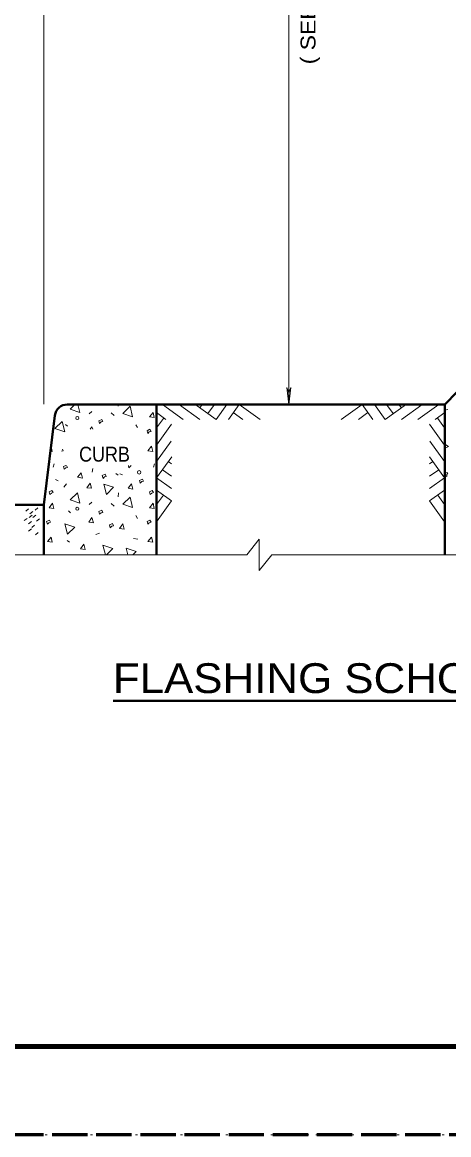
# Model space of a CAD drawing. Extents: x 312583 to 312854, y 144419 to 144597.
# Drawn here: x 312744.9 to 312766.7, y 144418.6 to 144475.3 of the extents above; entities that cross this region are included whole.
import ezdxf
from ezdxf.enums import TextEntityAlignment as Align

# ---------------------------------------------------------------- set-up
doc = ezdxf.new("R2010")
doc.units = 0
doc.header["$LTSCALE"] = 0.3
doc.linetypes.add('DOTTED', pattern=[1.5, 0.3, -1.2])
doc.linetypes.add('LONG_DASHED', pattern=[7.5, 6, -1.5])
for name, color, linetype, lineweight in [('1', 7, 'Continuous', 40), ('2', 7, 'Continuous', 13), ('62', 7, 'DOTTED', 13), ('63', 7, 'LONG_DASHED', 60)]:
    doc.layers.add(name, color=color, linetype=linetype, lineweight=lineweight)

msp = doc.modelspace()

# ---------------------------------------------------------------- linework, layer by layer
at = {"layer": '1'}
for p, q in [((312767.102, 144456.4563), (312766.4656, 144455.8123)), ((312766.4656, 144455.8123), (312747.2223, 144455.8123)), ((312751.7686, 144448.1456), (312751.7686, 144455.8123)), ((312766.4656, 144448.1456), (312766.4656, 144455.8123)), ((312746.586, 144455.2526), (312746.0186, 144450.7063)), ((312737.3329, 144450.7063), (312745.9655, 144450.7063)), ((312746.0186, 144448.1456), (312746.0186, 144450.7063))]:
    msp.add_line(p, q, dxfattribs=at)
at = {"layer": '1', "lineweight": 158}
msp.add_line((312616.5, 144423.0846), (312849, 144423.0846), dxfattribs=at)
at = {"layer": '1'}
msp.add_arc((312747.2222, 144455.1753), 0.6389, 90, 172.87498, dxfattribs=at)
at = {"layer": '2'}
for p, q in [((312746.0186, 144502.3183), (312746.0186, 144455.8276)), ((312758.5153, 144495.9933), (312758.5153, 144455.8123)), ((312758.408, 144456.6786), (312758.5153, 144456.4026)), ((312758.5153, 144455.8123), (312758.408, 144456.6786)), ((312758.408, 144456.6786), (312758.5153, 144456.4026)), ((312758.5153, 144455.8123), (312758.408, 144456.6786)), ((312758.6226, 144456.6786), (312758.5153, 144456.4026)), ((312758.5153, 144455.8123), (312758.6226, 144456.6786)), ((312758.6226, 144456.6786), (312758.5153, 144456.4026)), ((312758.5153, 144455.8123), (312758.6226, 144456.6786)), ((312748.334, 144455.3369), (312748.4796, 144455.4596)), ((312749.8213, 144455.8123), (312749.8136, 144455.7356)), ((312753.1333, 144455.0533), (312752.0676, 144455.8123)), ((312753.9766, 144455.0533), (312752.934, 144455.7969)), ((312754.8123, 144455.0533), (312753.7236, 144455.8276)), ((312754.0993, 144455.8123), (312753.9766, 144455.6436)), ((312754.728, 144455.8123), (312754.3906, 144455.3523)), ((312755.349, 144455.8123), (312754.8123, 144455.0533)), ((312755.9776, 144455.8123), (312755.4333, 144455.0533)), ((312757.051, 144455.0533), (312755.9776, 144455.8123)), ((312761.1833, 144455.0533), (312762.2566, 144455.8123)), ((312762.2566, 144455.8123), (312762.7933, 144455.0533)), ((312762.8853, 144455.8123), (312763.422, 144455.0533)), ((312763.422, 144455.0533), (312764.5106, 144455.8276)), ((312763.5063, 144455.8123), (312763.8436, 144455.3523)), ((312764.135, 144455.8123), (312764.2576, 144455.6436)), ((312764.2576, 144455.0533), (312765.2926, 144455.7969)), ((312765.101, 144455.0533), (312766.1666, 144455.8123)), ((312766.4733, 144455.5209), (312766.619, 144455.5593)), ((312749.461, 144455.3906), (312749.6143, 144455.2526)), ((312752.2516, 144455.0533), (312751.7686, 144455.3983)), ((312751.7763, 144454.6239), (312752.1213, 144455.1069)), ((312756.1693, 144455.0533), (312755.6786, 144455.3983)), ((312762.065, 144455.0533), (312762.548, 144455.3983)), ((312765.9826, 144455.0533), (312766.4656, 144455.3983)), ((312766.458, 144454.6239), (312766.113, 144455.1069)), ((312747.1303, 144454.7926), (312747.2376, 144454.7006)), ((312750.7106, 144454.7849), (312750.8026, 144454.6393)), ((312751.7763, 144453.7423), (312752.5353, 144454.8156)), ((312766.458, 144453.7423), (312765.699, 144454.8156)), ((312751.7763, 144452.8989), (312752.5123, 144453.9416)), ((312766.458, 144452.8989), (312765.7143, 144453.9416)), ((312746.3636, 144453.4279), (312746.4556, 144453.4126)), ((312746.5553, 144452.7916), (312746.5016, 144452.6153)), ((312750.335, 144452.6996), (312750.3656, 144452.5846)), ((312750.3656, 144452.5846), (312750.473, 144452.6996)), ((312751.669, 144452.7916), (312751.6153, 144452.6153)), ((312751.7763, 144452.0709), (312752.5506, 144453.1519)), ((312752.5353, 144452.7839), (312752.3666, 144452.8989)), ((312766.458, 144452.0709), (312765.6836, 144453.1519)), ((312765.699, 144452.7839), (312765.8676, 144452.8989)), ((312748.518, 144452.5463), (312748.4873, 144452.3699)), ((312749.691, 144452.3009), (312749.8136, 144452.2166)), ((312749.9056, 144452.2703), (312750.0436, 144452.2319)), ((312752.5353, 144451.5266), (312751.7763, 144452.0709)), ((312752.5353, 144452.1553), (312752.0676, 144452.4849)), ((312765.699, 144452.1553), (312766.159, 144452.4849)), ((312765.699, 144451.5266), (312766.458, 144452.0709)), ((312746.6166, 144451.9943), (312746.747, 144451.9176)), ((312747.1763, 144451.7643), (312747.046, 144451.5956)), ((312751.7303, 144451.9943), (312751.7686, 144451.9713)), ((312749.8366, 144451.3043), (312749.8136, 144451.1049)), ((312752.5353, 144450.8979), (312751.7763, 144451.4423)), ((312751.7763, 144450.7139), (312752.1213, 144451.1969)), ((312765.699, 144450.8979), (312766.458, 144451.4423)), ((312766.458, 144450.7139), (312766.113, 144451.1969)), ((312745.0986, 144450.3766), (312745.2443, 144450.4916)), ((312745.3133, 144450.2386), (312745.459, 144450.3536)), ((312745.574, 144450.4226), (312745.7196, 144450.5453)), ((312747.276, 144450.3843), (312747.3833, 144450.2846)), ((312748.334, 144450.7139), (312748.4796, 144450.8289)), ((312749.461, 144450.7599), (312749.6143, 144450.6219)), ((312751.7763, 144449.8323), (312752.5353, 144450.8979)), ((312766.458, 144449.8323), (312765.699, 144450.8979)), ((312745.0296, 144449.8936), (312745.1753, 144450.0086)), ((312745.2443, 144449.7326), (312745.3976, 144449.8476)), ((312745.2826, 144450.0469), (312745.4283, 144450.1696)), ((312745.4666, 144450.0469), (312745.62, 144450.1696)), ((312745.6506, 144449.8629), (312745.804, 144449.9779)), ((312750.7106, 144450.1619), (312750.8026, 144450.0086)), ((312745.2443, 144449.3569), (312745.3976, 144449.4719)), ((312745.4053, 144449.5486), (312745.551, 144449.6636)), ((312745.597, 144449.1653), (312745.7426, 144449.2803)), ((312748.8553, 144449.2573), (312748.679, 144449.1883)), ((312747.2146, 144448.8816), (312747.3296, 144448.7896)), ((312750.8256, 144448.9506), (312750.6033, 144448.9813)), ((312744.0636, 144448.1456), (312756.3686, 144448.1456)), ((312746.5553, 144448.1686), (312746.5476, 144448.1456)), ((312751.669, 144448.1686), (312751.669, 144448.1456)), ((312757.649, 144448.1456), (312772.2616, 144448.1456))]:
    msp.add_line(p, q, dxfattribs=at)
at = {"layer": '2', "lineweight": 40}
msp.add_line((312749.5561, 144440.7036), (312788.4573, 144440.7036), dxfattribs=at)
at = {"layer": '2'}
for points in [[(312747.6056, 144455.8123), (312747.368, 144455.5746), (312747.8663, 144455.4136), (312747.7666, 144455.8123)], [(312748.518, 144454.5473), (312748.4796, 144454.6776), (312748.3876, 144454.5473)], [(312766.4656, 144453.5813), (312766.6573, 144453.6733), (312766.4656, 144453.7883)], [(312746.4556, 144453.4126), (312746.3943, 144453.6809), (312746.3943, 144453.6809)], [(312746.9233, 144453.4279), (312747.0153, 144453.4509), (312746.9693, 144453.5429)], [(312747.1456, 144452.6996), (312747.0306, 144452.6459), (312747.069, 144452.5079), (312747.1456, 144452.5769)], [(312747.1456, 144452.5769), (312747.2376, 144452.6076), (312747.184, 144452.6996)], [(312766.5806, 144452.2473), (312766.6266, 144452.3239), (312766.5116, 144452.3623), (312766.4656, 144452.2473)], [(312766.4656, 144452.2013), (312766.5806, 144452.1399), (312766.5806, 144452.2473)], [(312757.649, 144448.1456), (312757.0126, 144447.3483), (312757.0126, 144448.9429), (312756.3686, 144448.1456)], [(312749.2156, 144448.1456), (312749.5376, 144448.4676), (312749.0393, 144448.6363), (312749.162, 144448.1456)], [(312750.5573, 144448.1456), (312750.726, 144448.3219), (312750.2276, 144448.4829), (312750.312, 144448.1456)]]:
    msp.add_lwpolyline(points, dxfattribs=at)
for points in [[(312750.4193, 144455.7203), (312750.059, 144455.3523), (312750.5496, 144455.1913)], [(312746.9616, 144454.9459), (312746.5936, 144454.5856), (312747.092, 144454.4169)], [(312748.9473, 144454.9229), (312749.0393, 144454.9459), (312748.978, 144455.0533), (312748.8323, 144454.9843), (312748.8706, 144454.8463)], [(312751.416, 144455.1759), (312751.6536, 144455.1453), (312751.5923, 144455.4059)], [(312751.4006, 144454.4169), (312751.4926, 144454.4399), (312751.4313, 144454.5473), (312751.2856, 144454.4783), (312751.324, 144454.3403)], [(312751.3316, 144453.4509), (312751.577, 144453.4126), (312751.508, 144453.6809)], [(312747.7436, 144452.1016), (312747.989, 144452.0633), (312747.92, 144452.3316)], [(312749.116, 144452.1246), (312749.208, 144452.1476), (312749.1543, 144452.2549), (312749.001, 144452.1936), (312749.047, 144452.0479)], [(312748.219, 144451.5726), (312748.4566, 144451.5419), (312748.3876, 144451.8026)], [(312749.2156, 144451.2276), (312749.576, 144451.5956), (312749.0853, 144451.7566)], [(312750.3196, 144451.5419), (312750.5573, 144451.5036), (312750.4883, 144451.7719)], [(312751.0173, 144451.8793), (312751.1093, 144451.9023), (312751.0556, 144452.0096), (312750.9023, 144451.9406), (312750.9406, 144451.8026)], [(312746.4096, 144451.2966), (312746.5016, 144451.3273), (312746.4403, 144451.4346), (312746.2946, 144451.3656), (312746.333, 144451.2276)], [(312747.736, 144451.3119), (312747.368, 144450.9516), (312747.8663, 144450.7829)], [(312750.4193, 144451.0896), (312750.059, 144450.7293), (312750.5496, 144450.5606)], [(312751.5233, 144451.2966), (312751.6153, 144451.3273), (312751.554, 144451.4346), (312751.4083, 144451.3656), (312751.4466, 144451.2276)], [(312746.3023, 144450.5453), (312746.54, 144450.5146), (312746.471, 144450.7753)], [(312748.9473, 144450.2923), (312749.0393, 144450.3153), (312748.978, 144450.4226), (312748.8323, 144450.3536), (312748.8706, 144450.2156)], [(312751.416, 144450.5453), (312751.6536, 144450.5146), (312751.5923, 144450.7753)], [(312746.287, 144449.7863), (312746.3713, 144449.8093), (312746.3176, 144449.9166), (312746.1643, 144449.8553), (312746.2103, 144449.7096)], [(312748.311, 144449.8169), (312748.5486, 144449.7863), (312748.4796, 144450.0546)], [(312751.4006, 144449.7863), (312751.4926, 144449.8093), (312751.4313, 144449.9166), (312751.2856, 144449.8553), (312751.324, 144449.7096)], [(312747.23, 144449.2036), (312747.598, 144449.5639), (312747.0996, 144449.7326)], [(312749.4916, 144449.6023), (312749.5836, 144449.6329), (312749.5223, 144449.7403), (312749.3766, 144449.6713), (312749.415, 144449.5333)], [(312749.8903, 144449.4949), (312750.128, 144449.4643), (312750.059, 144449.7249)], [(312746.218, 144448.8203), (312746.4556, 144448.7896), (312746.3943, 144449.0503)], [(312747.8893, 144448.4523), (312748.127, 144448.4216), (312748.058, 144448.6899)], [(312751.3316, 144448.8203), (312751.577, 144448.7896), (312751.508, 144449.0503)]]:
    msp.add_lwpolyline(points, close=True, dxfattribs=at)
for centre, radius in [((312747.7296, 144455.1248), 0.0784), ((312750.8863, 144452.3559), 0.0865), ((312747.7296, 144450.4967), 0.0784)]:
    msp.add_circle(centre, radius, dxfattribs=at)
at = {"layer": '62'}
msp.add_lwpolyline([(312601.2, 144418.5846), (312853.5, 144418.5846), (312853.5, 144596.7846)], dxfattribs=at)
at = {"layer": '63'}
msp.add_line((312851.75, 144418.5846), (312583.526, 144418.5846), dxfattribs=at)

# ---------------------------------------------------------------- texts
at = {"layer": '2', "width": 1.15}
msp.add_text('( SEE NOTE #1 )', height=0.76, rotation=90, dxfattribs=at).set_placement((312759.877, 144473.1561))
at = {"layer": '2', "width": 0.9}
msp.add_text('CURB', height=0.76, dxfattribs=at).set_placement((312747.8219, 144452.8998))
at = {"layer": '2', "width": 1.1}
msp.add_text('FLASHING SCHOOL ADVANCE SIGN', height=1.52, dxfattribs=at).set_placement((312768.9265, 144441.102), align=Align.CENTER)

doc.saveas('drawing.dxf')
